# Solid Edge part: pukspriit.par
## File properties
Author: Mac
Template: Normal.par
Last saved by: Mac
Revision: 11
Application: Solid Edge
Material: Epoxy, cast rigid
Face Style: White
Fill Style: ANSI34(Plastic)
Virtual Style: Shiny resin yellow
Coef. of Thermal Exp: 5.9e-05
Thermal Conductivity: 2.1
Specific Heat: 0.0
Modulus of Elasticity: 3102640650.0
Poission's Ratio: 0.37
Yield Stress: 65500191.5
Ultimate Stress: 0.0
Elongation: 0.0
Density: 1300,000 kg/m^3
Accuracy: 0,990
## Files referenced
..\..\paat abi3\Asm12.asm
BC:\Documents and Settings\Mac\Desktop\paat\Abi\paat abi3\Asm12.asm
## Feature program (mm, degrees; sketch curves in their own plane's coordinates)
sketch for "ExtrudedProtrusion_2" plane through (0, 0, 1) normal (0, 0, 1) x-axis (1, 0, 0)
extrude "ExtrudedProtrusion_2" add finite 5 along -normal
sketch for "unnamed Cutout 1" plane through (-7.3572, 4, -5) normal (0, -1, 0) x-axis (1, 0, 0)
extrude "unnamed Cutout 1" cut through
draft "Draft_1"  Angles1 = 45 deg
swept cutout "unnamed SweptCutout 1"
sketch for "unnamed Cutout 2" plane through (13.1598, 2.0731, -4) normal (0, 0, -1) x-axis (1, 0, 0)
  line (-15.6722, -2.0268) -> (13.3637, -0.8654)
  arc centre (13.3278, 0.0339) radius 0.9 from (13.3637, -0.8654) to (14.2278, 0.0339) ccw
  line (14.2278, 0.0339) -> (14.2278, 2.0731)
  line (14.2278, 2.0731) -> (-15.6722, 2.0731)
  line (-15.6722, 2.0731) -> (-15.6722, -2.0268)
extrude "unnamed Cutout 2" cut along +normal
fillet "Round_1" radius 0.2
fillet "Round_2" radius 0.2
fillet "Round_3" radius 0.2
body pattern "unnamed BodyPattern 1"
pattern "unnamed Pattern 1"
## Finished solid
Body 1: solid body, 100 faces, 233 edges, 134 vertices.
  Faces by surface: cylinder 40, plane 26, blend 14, torus 14, cone 2, sphere 2, spline 2
  Edges by curve: line 101, circle 90, intersection 36, ellipse 6
Bounding box of the edges (mm; curved faces can reach further): 45.308 x 11.200 x 5.000, from (-17.8202, -5.6, -4) to (27.4875, 5.6, 1).
Cylindrical faces by radius (mm): R0.0495 x4, R0.1 x4, R0.1016 x4, R0.15 x4, R0.2 x10, R0.3024 x4, R0.6024 x4, R0.9 x2, R1 x2, R688.137 x2
Conical faces (half-angle, radius in mm at the cone's reference point): 45 deg R1 x2
Toroidal faces (ring radius, tube radius in mm): R0.2007 r0.1016 x4, R0.4524 r0.15 x4, R0.6519 r0.0495 x4, R0.8 r0.2 x2
Spherical faces by radius (mm): R0.2 x2
Planar faces by outward normal: +x 4, +y 3, +z 3, -x 4, -y 3, -z 2, oblique 7
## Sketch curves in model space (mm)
line (-16.4226, 3.9, 1) -> (-16.4226, -3.9, 1)
line (-16.4226, 3.9, 1) -> (-16.4226, -3.9, 1)
arc centre (-16.1202, -3.9, 1) radius 0.6024 from (-16.1202, -4.5024, 1) through (-16.5584, -4.3134, 1) to (-16.7226, -3.9, 1)
line (-8.3202, -4.5024, 1) -> (-16.1202, -4.5024, 1)
arc centre (-8.3202, -3.9, 1) radius 0.6024 from (-7.7179, -3.9, 1) through (-7.9069, -4.3381, 1) to (-8.3202, -4.5024, 1)
line (-7.7179, -3.9, 1) -> (-7.7179, 3.9, 1)
arc centre (-8.3202, 3.9, 1) radius 0.6024 from (-7.7179, 3.9, 1) through (-7.9069, 4.3381, 1) to (-8.3202, 4.5024, 1)
line (-8.3202, 4.5024, 1) -> (-16.1202, 4.5024, 1)
arc centre (-16.1202, 3.9, 1) radius 0.6024 from (-16.1202, 4.5024, 1) through (-16.5584, 4.3134, 1) to (-16.7226, 3.9, 1)
line (-16.7226, 3.9, 1) -> (-16.7226, -3.9, 1)
arc centre (-16.1202, 3.9, 1) radius 0.3024 from (-16.1202, 4.2024, 1) through (-16.3402, 4.1075, 1) to (-16.4226, 3.9, 1)
arc centre (-16.1202, -3.9, 1) radius 0.3024 from (-16.1202, -4.2024, 1) through (-16.3402, -4.1075, 1) to (-16.4226, -3.9, 1)
line (-8.3202, -4.2024, 1) -> (-16.1202, -4.2024, 1)
arc centre (-8.3202, -3.9, 1) radius 0.3024 from (-8.0179, -3.9, 1) through (-8.1127, -4.1199, 1) to (-8.3202, -4.2024, 1)
line (-8.0179, -3.9, 1) -> (-8.0179, 3.9, 1)
arc centre (-8.3202, 3.9, 1) radius 0.3024 from (-8.0179, 3.9, 1) through (-8.1127, 4.1199, 1) to (-8.3202, 4.2024, 1)
line (-8.3202, 4.2024, 1) -> (-16.1202, 4.2024, 1)
arc centre (-16.321, 6.7, 0.8) radius 0.1016 from (-16.4226, 6.7, 0.8) through (-16.3277, 6.7, 0.9014) to (-16.2202, 6.7, 0.8134)
line (-16.2202, 6.7, 0) -> (-16.2202, 6.7, 0.8134)
arc centre (-16.5726, 6.7, 0.7906) radius 0.15 from (-16.7226, 6.7, 0.7906) through (-16.5681, 6.7, 0.6406) to (-16.4226, 6.7, 0.7906)
line (-16.7226, 6.7, 0.9505) -> (-16.7226, 6.7, 0.7906)
arc centre (-7.8679, 0, 0.7906) radius 0.15 from (-7.7179, 0, 0.7906) through (-7.8723, 0, 0.6406) to (-8.0179, 0, 0.7906)
line (-7.7179, 0, 0.9505) -> (-7.7179, 0, 0.7906)
arc centre (-7.6683, 0, 0.9505) radius 0.0495 from (-7.7179, 0, 0.9505) through (-7.7023, 0, 0.9865) to (-7.6683, 0, 1)
line (-7.6683, 0, 1) -> (-7.6683, 0, 1.0485)
line (-7.6683, 0, 1.0485) -> (-8.2688, 0, 1.0485)
line (-8.2688, 0, 1.0485) -> (-8.2688, 0, 0.8134)
line (-8.2688, 0, 0.8134) -> (-8.2202, 0, 0.8134)
arc centre (-8.1195, 0, 0.8) radius 0.1016 from (-8.2202, 0, 0.8134) through (-8.1128, 0, 0.9014) to (-8.0179, 0, 0.8)
line (-8.0179, 0, 0.8) -> (-8.0179, 0, 0.7906)
line (0.3896, 4, -4.9) -> (-0.8692, 4, -4.9)
arc centre (-654.114, 4, -221.242) radius 688.137 from (-0.8692, 4, -4.9) through (-1.6862, 4, -2.4485) to (-2.5125, 4, 0)
line (-2.5125, 4, 0) -> (-22.5125, 4, 0)
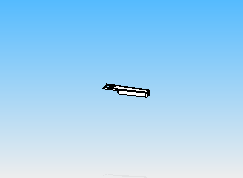
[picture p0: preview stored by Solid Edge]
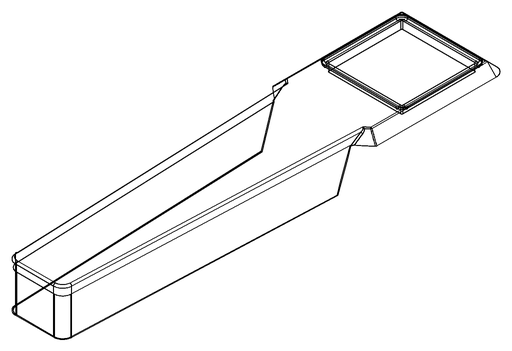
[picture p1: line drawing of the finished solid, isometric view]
